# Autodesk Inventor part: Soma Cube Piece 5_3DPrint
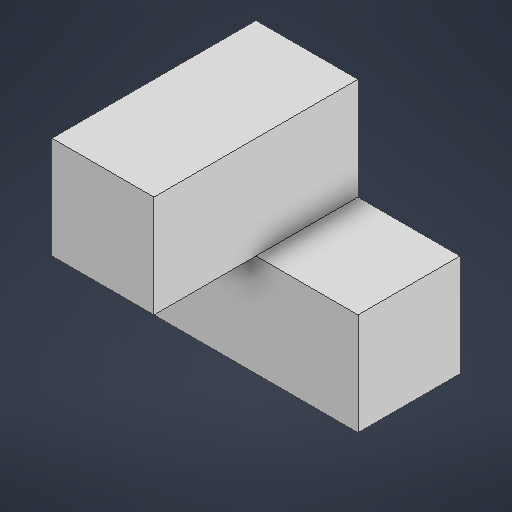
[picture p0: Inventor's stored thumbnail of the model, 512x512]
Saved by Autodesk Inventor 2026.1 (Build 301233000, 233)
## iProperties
Created: 2025-12
Part Number: Soma Cube Piece 5_3DPrint
Material: Generic
Document SubType Name: Modeling
Designer: egberbos000
Density: 1 g/cm^3
Appearance: Default
Author: egberbos000
Part Number: Soma Cube Piece 5
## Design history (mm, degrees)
sketch "Sketch1"
  geometry: L1 (0, 0)-(50.8, 0); L2 (50.8, 0)-(50.8, 25.4); L3 (50.8, 25.4)-(0, 25.4); L4 (0, 25.4)-(0, 0); L5 (25.4, 25.4)-(0, 25.4); L6 (0, 25.4)-(0, 50.8); L7 (0, 50.8)-(25.4, 50.8); L8 (25.4, 50.8)-(25.4, 25.4)
  constraints: 16 end point, 4 parallel, 2 horizontal, 2 perpendicular, 1 midpoint
  dimensions: "d0" = 50.8 distance of L2.end L3.end; "d1" = 25.4 distance of L1.end L2.end; "d2" = 25.4 distance of L5.end L6.end; "d3" = 25.4 distance of L6.end L7.end
extrude "Extrusion1" new body sketch "Sketch1" distance "d4" = 25.4; taper "d5" = 0 deg
sketch "Sketch2"
  geometry: L1 (50.8, 25.4)-(0, 25.4) reference; L2 (25.4, 25.4)-(0, 25.4); L3 (0, 25.4)-(0, 50.8); L4 (0, 50.8)-(25.4, 50.8); L5 (25.4, 50.8)-(25.4, 25.4); 2 further points
  constraints: 8 end point, 2 parallel, 1 horizontal, 1 midpoint, 1 perpendicular
  dimensions: "d6" = 25.4 distance of L3.end L4.end; "d7" = 25.4 distance of L2.end L3.end
extrude "Extrusion2" join sketch "Sketch2" distance "d8" = 25.4; taper "d10" = 0 deg; dims "d9" = 25.4, "d11" = 0
body "Solid1"
